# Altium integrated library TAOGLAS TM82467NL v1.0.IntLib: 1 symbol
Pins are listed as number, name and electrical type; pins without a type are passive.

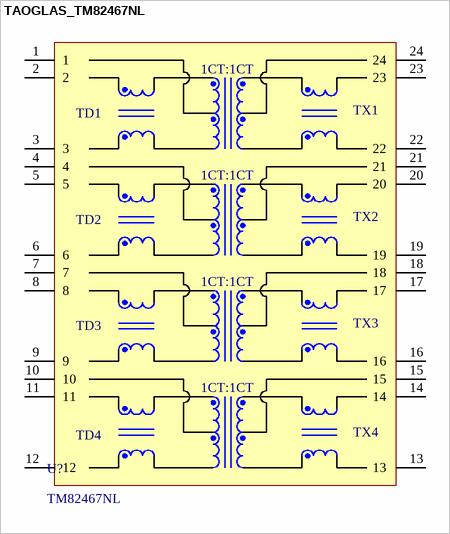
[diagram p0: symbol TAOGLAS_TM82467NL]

## TAOGLAS_TM82467NL
designator U?, comment TM82467NL
1G Base-T transformer Single Port and 24pin SMT with PoE; ComponentLibStatus: Created; MFG: Taoglas; Temp_High: +85C; Temp_Low: -40C
footprint TAOGLAS_TM82467NL (1G Base-T transformer Single Port and 24pin SMT with PoE)
pins: 1, 2, 3, 4, 5, 6, 7, 8, 9, 10, 11, 12, 13, 14, 15, 16, 17, 18, 19, 20, 21, 22, 23, 24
